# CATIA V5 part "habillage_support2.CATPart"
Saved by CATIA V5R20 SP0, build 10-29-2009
Part number: habillage_support2
Bounding box of the stored display mesh (mm): x -10 to 0, y -60 to 360, z -10 to 10
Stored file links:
  C:\Users\Noëllie\Documents\IFMA\2A\S3\IAO\Projet Artobolevski\Catia\habillage_support2.CATPart
  C:\Users\Noëllie\Documents\IFMA\2A\S3\IAO\Projet Artobolevski\Catia\assemblage_balance.CATProduct
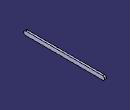
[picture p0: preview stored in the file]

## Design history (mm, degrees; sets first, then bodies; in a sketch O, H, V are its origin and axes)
Parameters
  h = 20 mm
  b = 10 mm
Set1
  Point1 "B2g": linked copy from another document
  Point2 "B2d": linked copy from another document
Body1 (main body)
  Sketch1 on yz-plane, origin (0, 0, 0), H (0, 1, 0), V (0, 0, 1)
    line L1 (-50, 10) -> (350, 10)
    line L2 (-50, -10) -> (350, -10)
    point P5 (40, 0)
    arc A1 centre (350, 0) radius 10 from (350, 10) to (350, -10) cw
    point P6 (350, 0)
    arc A2 centre (-50, 0) radius 10 from (-50, 10) to (-50, -10) ccw
    point P7 (-50, 0)
    reference projected point E1 (-50, 0) from Point1
    reference projected point E2 (350, 0) from Point2
    distance L1 L2 = 20 {= h}
    length L1 = 400
    horizontal: L1 H, L2 H
    coincidence: P5 H, P7 E1, P6 E2
    tangency: A1 L2, A2 L2
  Pad1: profile Sketch1, direction (1, 0, 0), length 0, opposite side length 10 {= b}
